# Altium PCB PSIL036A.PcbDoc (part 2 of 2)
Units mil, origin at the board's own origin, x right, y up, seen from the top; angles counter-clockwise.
Board outline 2820.01 x 3610.03 mil, 2 copper layers (Top Layer, Bottom Layer), stack 62 mil thick; 102 components, 95 nets, 316 pads, 73 vias.
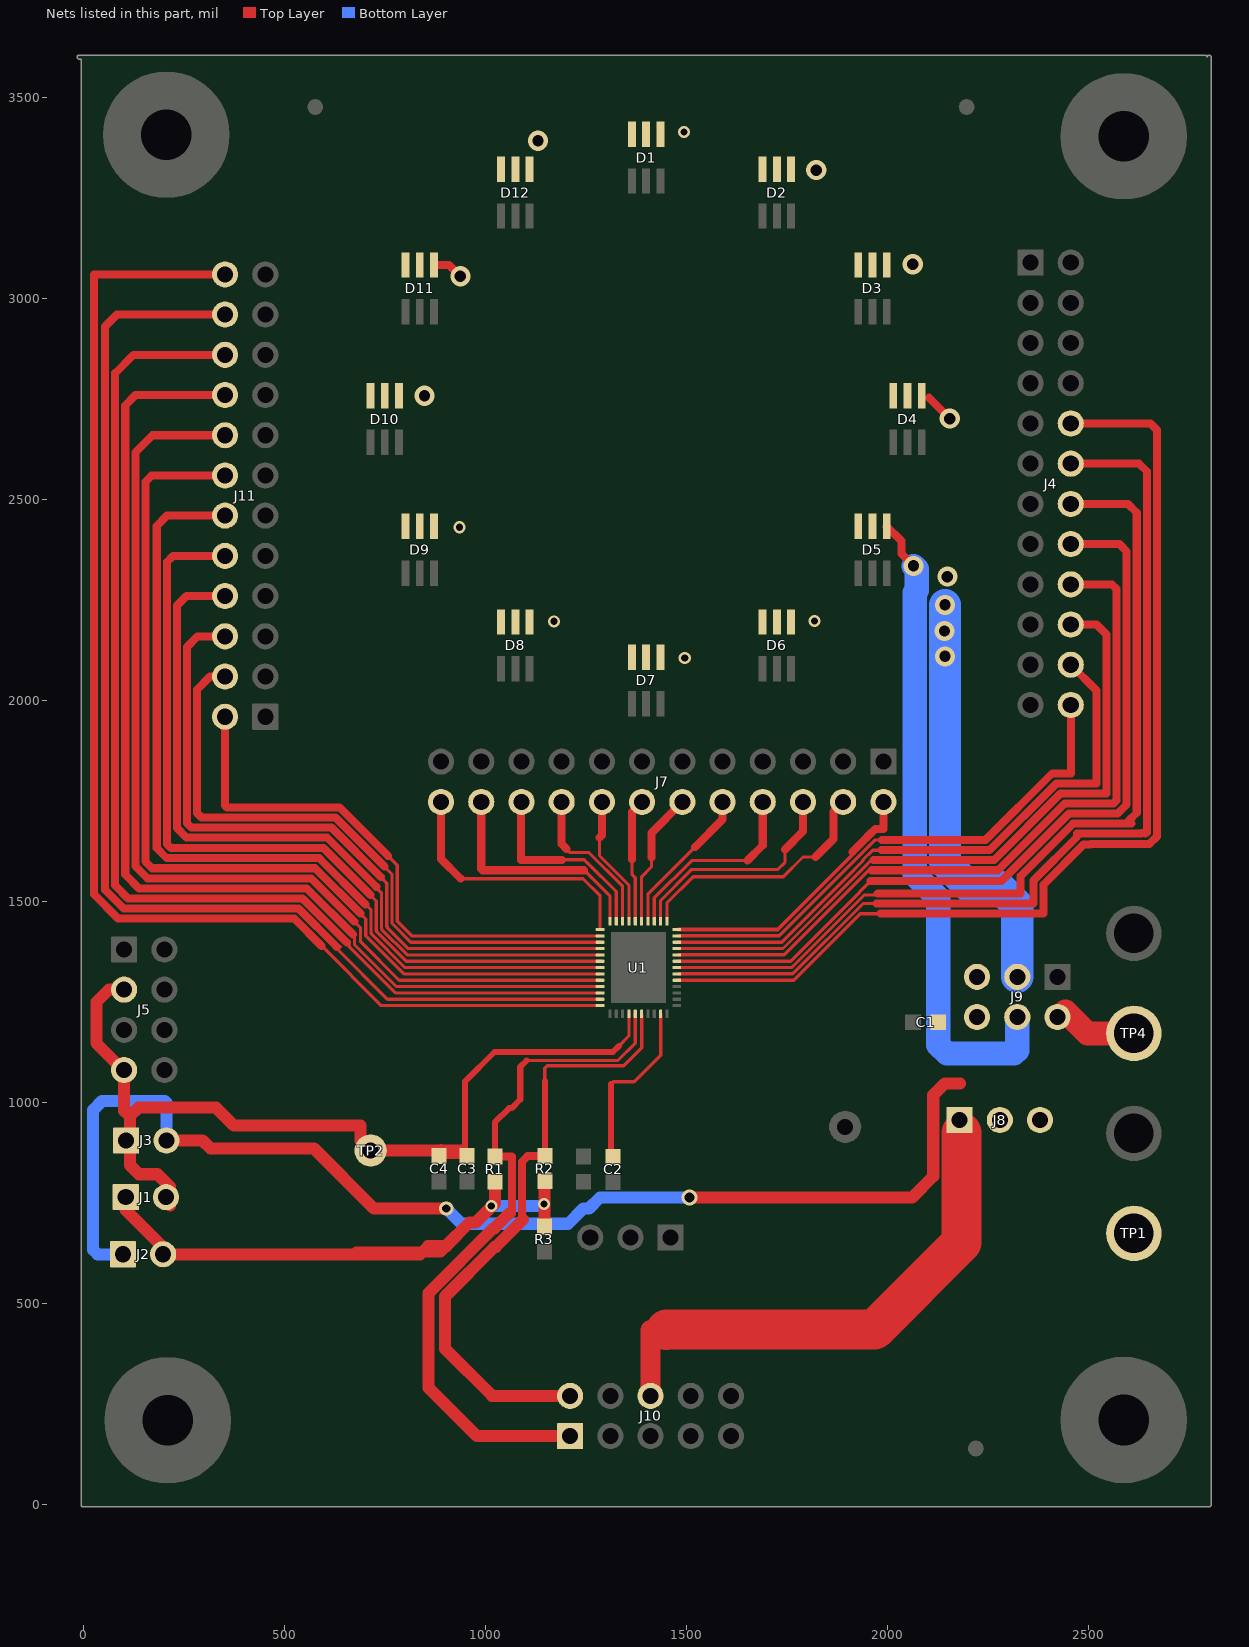
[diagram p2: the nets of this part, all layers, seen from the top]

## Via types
v1: diameter 50, hole 28, Top Layer to Bottom Layer, 48 vias
v2: diameter 19.68, hole 7.87, Top Layer to Bottom Layer, 16 vias
v3: diameter 30, hole 18, Top Layer to Bottom Layer, 7 vias
v4: diameter 35, hole 20, Top Layer to Bottom Layer, 1 vias
v5: diameter 40, hole 25, Top Layer to Bottom Layer, 1 vias

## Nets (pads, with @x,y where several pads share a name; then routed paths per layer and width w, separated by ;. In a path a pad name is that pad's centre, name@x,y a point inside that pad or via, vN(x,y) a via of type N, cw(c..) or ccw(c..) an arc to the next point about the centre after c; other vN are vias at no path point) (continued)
OUT4: J4.10 U1.5 | length 2612.8
  Top Layer w8: U1.5@1479.17,1304.63 1767.25,1304.63 1932.62,1470 1983,1470
  Top Layer w20: 1983,1470 2388,1470 2388,1542.07 2487.93,1642 2504.18,1642 2506,1643.82 2652,1643.82 2670,1661.82 2670,2673 2654,2689 J4.10@2455.99,2689
OUT5: J4.12 U1.6 | length 2434.9
  Top Layer w8: U1.6@1479.17,1320.38 1764.61,1320.38 1939.23,1495 1972.64,1495
  Top Layer w20: 1972.64,1495 2363,1495 2363,1552.42 2472,1661.42 2472,1668.82 2630.64,1668.82 2631.82,1670 ; J4.12@2455.99,2589 2626,2589 2645,2570 2645,1672.18 2641.64,1668.82
OUT6: J4.14 U1.7 | length 2258.7
  Top Layer w8: U1.7@1479.17,1336.13 1761.97,1336.13 1942.38,1516.53 1972.53,1516.53 1976,1520
  Top Layer w20: 1976,1520 2331,1520 2331,1563.18 2461.64,1693.82 2606.82,1693.82 2599.83,1700.82 2620,1720.99 2620,2467 2598,2489 J4.14@2455.99,2489
OUT7: J4.16 U1.8 | length 2053.7
  Top Layer w8: U1.8@1479.17,1351.87 1759.34,1351.87 1931.23,1523.77 1931.23,1524.3 1958.47,1551.53
  Top Layer w20: 1958.47,1551.53 2284,1551.53 2451.29,1718.82 2572.65,1718.82 2595,1741.17 2595,2371 2577,2389 J4.16@2455.99,2389
OUT8: J4.18 U1.9 | length 1894
  Top Layer w8: U1.9@1479.17,1367.62 1743.01,1367.62 1953.38,1578 1961,1578
  Top Layer w20: 1961,1578 2275.11,1578 2440.93,1743.82 2561.82,1743.82 2570,1752 2570,2277 2558,2289 J4.18@2455.99,2289
OUT9: J4.20 U1.10 | length 1720.6
  Top Layer w8: U1.10@1479.17,1383.37 1740.37,1383.37 1942,1585 1942,1585.87 1959.13,1603 1965,1603
  Top Layer w20: 1965,1603 2264.76,1603 2430.76,1769 2519,1769 ; J4.20@2455.99,2189 2520,2189 2545,2164 2545,1768.82 2519,1768.82
OUT10: J4.22 U1.11 | length 1527.9
  Top Layer w8: U1.11@1479.17,1399.12 1737.73,1399.12 1897.47,1558.85 1897.47,1559.72 1939.37,1601.63 1939.37,1604.24 1963.13,1628 1985,1628
  Top Layer w20: 1985,1628 2254.4,1628 2420.4,1794 2520,1794 2520,2024.99 J4.22@2455.99,2089
OUT11: J4.24 U1.12 | length 1314.7
  Top Layer w8: U1.12@1479.17,1414.87 1730.87,1414.87 1968.13,1652.13 1968.13,1653 1986,1653
  Top Layer w20: 1986,1653 2244.05,1653 2410.05,1819.01 2455.99,1819.01 J4.24@2455.99,1989
OUT12: J7.2 U1.13 | length 690
  Top Layer w9: U1.13@1479.17,1430.61 1727.52,1430.61 1916.95,1620.05
  Top Layer w15: J7.2@1990,1748 J7.2@1994,1744
  Top Layer w20: 1913.07,1623.94 1949.13,1660 1949.13,1660.87 1960.26,1672 1961.13,1672 1970.13,1681 1990,1681 J7.2@1990,1748
OUT13: J7.4 U1.14 | length 620.8
  Top Layer w8: U1.14@1451.61,1458.17 1451.61,1496.61 1517,1562 1741,1562 1790,1611 1821,1611
  Top Layer w20: 1821,1611 1866,1656 1866,1724 J7.4@1890,1748
OUT14: J7.6 U1.15 | length 562.5
  Top Layer w8: U1.15@1435.87,1458.17 1435.87,1502.87 1513,1580 1728,1580 1745,1597 1745,1630
  Top Layer w20: 1745,1630 1790,1675 J7.6@1790,1748
OUT15: J7.8 U1.16 | length 495.8
  Top Layer w8: U1.16@1420.12,1458.17 1420.12,1509.12 1513,1602 1652,1602
  Top Layer w15: J7.8@1681,1739 J7.8@1690,1748
  Top Layer w20: 1652,1602 1690,1640 J7.8@1690,1748
OUT16: J7.10 U1.17 | length 382.3
  Top Layer w8: U1.17@1404.37,1458.17 1404.37,1518.37 1522,1636
  Top Layer w15: J7.10@1590,1748 J7.10@1601,1737
  Top Layer w20: 1522,1636 1590,1704 J7.10@1590,1748
OUT17: J7.12 U1.18 | length 331.8
  Top Layer w8: U1.18@1388.62,1458.17 1388.62,1561.62 1413,1586 1413,1610
  Top Layer w20: 1413,1610 1413,1671 J7.12@1490,1748
OUT18: J7.14 U1.19 | length 303.4
  Top Layer w8: 1365,1605 1365,1567 1372.87,1559.13 U1.19@1372.87,1458.17
  Top Layer w20: 1365,1605 1365,1723 J7.14@1390,1748
OUT19: J7.16 U1.20 | length 322.6
  Top Layer w8: 1284,1659 1284,1614.38 1357.13,1541.26 U1.20@1357.13,1458.17
  Top Layer w20: 1284,1659 1290,1665 J7.16@1290,1748
OUT20: J7.18 U1.21 | length 380.1
  Top Layer w8: 1202,1631 1211,1622 1258,1622 1341.38,1538.62 U1.21@1341.38,1458.17
  Top Layer w20: J7.18@1190,1748 1190,1643 1202,1631
OUT21: J7.20 U1.22 | length 480.7
  Top Layer w8: 1191,1604 1246,1604 1253,1597 1253.87,1597 1325.63,1525.24 U1.22@1325.63,1458.17
  Top Layer w20: J7.20@1090,1748 1089,1747 1089,1604 1191,1604
OUT22: J7.22 U1.23 | length 570.5
  Top Layer w8: 1246,1578 1309.88,1514.12 U1.23@1309.88,1458.17
  Top Layer w20: J7.22@990,1748 990,1581 993,1578 1246,1578
OUT23: J7.24 U1.24 | length 659.4
  Top Layer w8: 939,1557 1243,1557 1285.53,1514.47 U1.24@1285.53,1430.49
  Top Layer w20: J7.24@890,1748 890,1606 939,1557
OUT24: J11.2 U1.25 | length 1369.3
  Top Layer w8: 757.95,1613.95 781.03,1590.88 781.03,1451.38 817.68,1414.74 U1.25@1285.53,1414.74
  Top Layer w20: J11.2@353,1959.76 353,1739 358,1734 637.91,1734 757.95,1613.95
OUT25: J11.4 U1.26 | length 1597.8
  Top Layer w8: 749.28,1587.28 768.03,1568.52 768.03,1446 815.04,1398.99 U1.26@1285.53,1398.99
  Top Layer w20: J11.4@353,2059.76 315.76,2059.76 283,2027 283,1720 294,1709 627.55,1709 749.28,1587.28
OUT26: J11.6 U1.27 | length 1765
  Top Layer w8: 740.1,1561.1 755.03,1546.16 755.03,1439.51 755.03,1438.51 756.03,1437.51 756.03,1435.51 808.29,1383.24 U1.27@1285.53,1383.24
  Top Layer w20: J11.6@353,2159.76 284.76,2159.76 258,2133 258,1695 269,1684 617.2,1684 740.1,1561.1
OUT27: J11.8 U1.28 | length 1919.5
  Top Layer w8: 727.5,1535.5 742.03,1520.97 742.03,1433.12 743.03,1432.12 743.03,1430.12 805.66,1367.5 U1.28@1285.53,1367.5
  Top Layer w20: J11.8@353,2259.76 256.76,2259.76 233,2236 233,1683 257,1659 606.84,1659 728.92,1536.92
OUT28: J11.10 U1.29 | length 2094.8
  Top Layer w8: 714.24,1516.24 729.03,1501.45 729.03,1427.74 730.03,1426.74 730.03,1424.74 803.02,1351.75 U1.29@1285.53,1351.75
  Top Layer w20: J11.10@353,2359.76 223.76,2359.76 208,2344 208,1643.36 218.36,1633 597.49,1633 714.24,1516.24
OUT29: J11.12 U1.30 | length 2241.2
  Top Layer w8: 702.07,1493.07 716.03,1479.1 716.03,1422.35 717.03,1421.35 ; 716.03,1420.35 800.38,1336 U1.30@1285.53,1336
  Top Layer w20: J11.12@353,2459.76 208.44,2459.76 183,2434.32 183,1633 208,1608 587.13,1608 702.07,1493.07
OUT30: J11.14 U1.31 | length 2420.4
  Top Layer w8: 689.39,1470.39 703.03,1456.74 703.03,1414.97 797.75,1320.25 U1.31@1285.53,1320.25
  Top Layer w20: J11.14@353,2559.76 170.44,2559.76 154.68,2544 154.68,1599.32 171,1583 576.78,1583 689.39,1470.39
OUT31: J11.16 U1.32 | length 2563.3
  Top Layer w8: 674.21,1450.21 690.03,1434.39 690.03,1399.97 785.5,1304.5 U1.32@1285.53,1304.5
  Top Layer w20: J11.16@353,2659.76 172.44,2659.76 129.68,2617 129.68,1588.32 160,1558 566.42,1558 674.21,1450.21
OUT32: J11.18 U1.33 | length 2734.2
  Top Layer w8: 671.03,1418.03 671.03,1413.19 674.68,1409.55 674.68,1393.32 779.24,1288.76 U1.33@1285.53,1288.76
  Top Layer w20: J11.18@353,2759.76 130.44,2759.76 104.68,2734 104.68,1567.32 139,1533 556.07,1533 671.03,1418.03
OUT33: J11.20 U1.34 | length 2885.3
  Top Layer w8: 655.68,1398.03 661.68,1392.03 661.68,1387.94 776.61,1273.01 U1.34@1285.53,1273.01
  Top Layer w20: J11.20@353,2859.76 125.44,2859.76 79.68,2814 79.68,1539.68 111.36,1508 545.71,1508 655.68,1398.03
OUT34: J11.22 U1.35 | length 3061.5
  Top Layer w8: 630.68,1383.32 756.74,1257.26 U1.35@1285.53,1257.26 ; 630.68,1387.68 639.16,1387.68
  Top Layer w20: J11.22@353,2959.76 84.52,2959.76 54.68,2929.92 54.68,1529.32 101,1483 535.36,1483 630.68,1387.68
OUT35: J11.24 U1.36 | length 3241.2
  Top Layer w8: 593,1390 741.49,1241.51 U1.36@1285.53,1241.51
  Top Layer w20: J11.24@353,3059.76 26.76,3059.76 26.76,1518.24 87,1458 525,1458 593,1390
SCL: J10.2 R2.1 U1.42 | length 1537
  Top Layer w8: 1148,1054 1148,1086 1154,1092 1344,1092 1388.87,1136.87 U1.42@1388.87,1220.84
  Top Layer w15: R2.1@1148,867.5 1148,1054
  Top Layer w20: 1091,706.57 1091,852.99 1105.5,867.5 R2.1@1148,867.5
  Top Layer w30: 1094.21,709.79 1091,706.57 1026.18,641.75 1023.75,641.75 900,518 900,388 1017,271 J10.2@1211,271
SDA: J10.1 R1.1 U1.41 | length 1744.6
  Top Layer w8: 1103,1105 1330,1105 1373.13,1148.13 U1.41@1373.13,1220.84
  Top Layer w15: R1.1@1024,866.5 1024,951 1059.5,986.5 1065.5,986.5 1087,1008 1087,1089 1103,1105
  Top Layer w20: R1.1@1024,866.5 1065.85,866.5 1067,865.35 1066,864.35 1066,724 1064.54,722.54
  Top Layer w30: 1061,726.07 1022.46,687.54 1020.04,687.54 859,526.5 859,291 979,171 J10.1@1211,171
VBG: D1.5 D1.6 D2.5 D2.6 D3.5 D3.6 D4.5 D4.6 D5.5 D5.6 D6.5 D6.6 D7.5 D7.6 D8.5 D8.6 D9.5 D9.6 D10.5 D10.6 D11.5 D11.6 D12.5 D12.6 J9.3 | length 1042.2
  Bottom Layer w80: v1(2143,2238) v1(2143,2110) 2143,1597.82 2202.34,1538.48 2275.09,1538.48 2323,1490.57 J9.3@2323,1313
  other v1: 2142,2173 2149,2308
VCAP: C2.1 U1.45 | length 438.9
  Top Layer w8: 1313,1047 1318,1052 1370,1052 1436.12,1118.12 U1.45@1436.12,1220.84
  Top Layer w15: 1313,1047 1313,870.5 C2.1@1318,865.5
VCC: C3.1 C4.1 J1.2 J3.1 J5.3 J5.7 TP2.1 U1.40 | length 2358.4
  Top Layer w8: 1332.17,1140.83 1357.38,1166.04 U1.40@1357.38,1220.84
  Top Layer w15: C4.1@896,875.2 904,867.2 C3.1@955,867.2 C3.1@962,867.2 ; C3.1@950,874.5 950,1053 1023,1126 1317.33,1126 1332.17,1140.83
  Top Layer w30: J5.3@100,1281 64,1281 33,1250 33,1148 100,1081 J5.7@102,1081 102,980 116,966 ; J1.2@216,744 216,791 185,822 139,822 116,845 116,966 ; C4.1@889.5,881.7 C4.1@896,875.2 ; C3.1@943.5,881 TP2.1@715,881 690,906 690,943 375,943 330,988 138,988 116,966
VIN_EXT: J8.3 TP1.1
VINL: J8.1 J10.6 | length 1299.9
  Top Layer w50: J10.6@1411,271 1411,435 1450,435
  Top Layer w100: 1450,435 1451,436 1968,436 2184,652 J8.1@2184,925
VLED: C1.1 J2.1 J3.2 J8.2 J9.5 J9.6 | length 3036
  Top Layer w30: J3.2@207,906 297,906 317,886 574,886 723,737 v4(903,737) ; v5(1508,764) 2061,764 2114,817 2114,1019 2143,1048 2181,1048
  Bottom Layer w30: J2.1@99,623 36,623 25,634 25,982 47,1004 203,1004 207,1000 J3.2@207,906 ; v4(903,737) 941,699 1206,699 1244,737 1258,737 1285,764 v5(1508,764)
VMCU: J1.1 J2.2 R1.2 R2.2 R3.2 | length 1570.2
  Top Layer w30: J1.1@106,765 106,733 199,640 J2.2@199,623 675.44,623 ; R1.2@1024,803.5 1024,750 975.75,701.75 960.5,701.75 902.38,643.62 ; R3.2@1147,705.5 1147,803.5 R2.2@1148,804.5 ; 675.44,623 838.01,623 842.01,627 ; 675.44,623 679.44,627 842.01,627 ; 842.01,627 844.5,629.5 ; 844.5,629.5 888.25,629.5 901.75,643 ; 844.5,629.5 858.01,643 901.75,643 ; 901.75,643 903,643 902.38,643.62 ; 901.75,643 902.38,643.62
  Bottom Layer w30: v3(1015,743) v3@1141,743
  other v3: 1146,748
VR: D1.4 D2.4 D3.4 D4.4 D5.4 D6.4 D7.4 D8.4 D9.4 D10.4 D11.4 D12.4 J9.4 | length 1789.1
  Top Layer w20: D11.4@872.53,3083.07 909.93,3083.07 v1(938,3055) ; D5.4@1998.33,2433.07 2035,2396.4 2035,2365 v1(2065,2335) ; 2103,2753 v1(2155,2701)
  Bottom Layer w60: v1(2065,2335) 2072.97,2327.03 2072.97,2274.03 2068,2269.07 2068,1566.75 2126.5,1508.25 2126.5,1143.5 2148,1122 2315,1122 2323,1130 J9.4@2323,1213
  other v1: 849,2758 2063,3085 1823,3319 1131,3392
  other v3: 1496,2106 1171,2197 1819,2198 936,2431 1494,3414
VR_EXT: J9.2 TP4.1 | length 188.6
  Top Layer w60: J9.2@2443,1227 2497.67,1172.33 TP4.1@2609,1172.33
pads on no net: FID1.1 FID2.1 FID3.1 H1.0 H2.1 H3.0 H4.1 H5.0 H6.1 H7.0 H8.1 J9.1 SH1.0 SH2.0 SH3.0 SH4.0 SH5.0 SH6.0 SH7.0 SH8.0 SH9.0 SH10.0 SH11.0 SH12.0 SH13.0 SH14.0 SH15.0 SH16.0 SH17.0 SH18.0 SH19.0 SH20.0 SH21.0 SH22.0 SH23.0 SH24.0 SH25.0 SH26.0 SH27.0 SH28.0 SH29.0 SH30.0 SH31.0 SH32.0 SH33.0 SH34.0 SH35.0 SH36.0 SH37.0 SH38.0 SH39.0 SH40.0 SH41.0 SH42.0 SH43.0 SH44.0 U1.

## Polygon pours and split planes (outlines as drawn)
VBG on Top Layer "VBG_L01_P024" (solid, remove dead copper, pour order 24): 1052,2147 1266,2147 1268,2145 1259,2136 1259,2023 1637,2023 1654,2040 1654,2127 1858,2127 1896,2165 1896,2365 2084,2365 2098,2351 2140,2393 2140,3118 1765,3493 984,3493 897,3406 897,3238 866,3207 659,3207 659,2169 679,2149
VBG on Top Layer "VBG_L01_P026" (solid, remove dead copper, pour order 26): 1966,2558 1966,2085 2015,2036 2035,2056 2271,2056 2271,2527 2252,2546 1976,2546
GND on Top Layer "GND_L01_P032" (solid, remove dead copper, pour order 32): 13,3604 17,3600 2800,3600 2800,11 2789,0 0,0 0,3559.6 12.24,3571.83
VR on Bottom Layer "VR_L02_P028" (solid, remove dead copper, pour order 28): 801,3164 801,2300 1044,2057 1751.49,2057 1926.49,2232 2055,2232 2099,2276 2099,2628.36 2097.36,2630 2125.36,2658 2205,2658 2205,3033 2062,3176 2062,3195 1902,3195 1896,3189 1869,3216 1869,3399 1583,3399 1529,3453 1529,3459 1067,3459 804,3196 804,3164
GND on Bottom Layer "GND_L02_P030" (solid, remove dead copper, pour order 30): -15,3600 -3,3612 2801,3612 2801,1 2800,0 2787,13 2,13 2,3598 0,3600

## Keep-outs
Keep-Out Layer:
  lines w10: -10,3600 2790,3600 ; 0,3600 0,0 2800,0 2800,3600
  text ".Layer_Name" at -673,-1908.49 h60

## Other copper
Top Layer:
  rectangle net VINL: 1379,262 1443,476.65
  rectangle net VIN_EXT: 2393,598 2690,725
  rectangle net VIN_EXT: 2390.86,621 2508,907
  rectangle net VCC: 881,854.4 962,890.7
  rectangle net VLED: 2169,1127 2279,1352
  rectangle net VLED: 2171,1028 2280,1208
  rectangle net VLED: 2165,1010 2365,1119
  rectangle net VIN_EXT: 2397,809 2502,1000
  rectangle net VLED: 2115,1159 2187,1239
  rectangle net VBG: 700,2734.95 756,2823
  rectangle net VR: 781,2725 874,2790
  rectangle net VBG: 795,2410 842,2519
  rectangle net VR: 873,2403 955,2471
  rectangle net VR: 1108,2167 1190,2236
  rectangle net VR: 1435,2072 1530,2149
  rectangle net VR: 1761,2165 1848,2237
  rectangle net VR: 2081,2733 2122,2785
  rectangle net VR: 1993,3048 2098,3133
  rectangle net VR: 1753,3290 1860,3355
  rectangle net VR: 1437,3377 1519,3440
  rectangle net VR: 1107,3295 1149,3411
  rectangle net VBG: 2099,2042 2199,2377
  rectangle net VLED: 2242,892 2330,1128
  rectangle net VINL: 2139,865 2228,964
  rectangle net VR_EXT: 2399,1126 2633,1229
  rectangle net VIN_EXT: 2348,898 2464,993
  text ".Layer_Name" at -673,-1908.49 h60
Bottom Layer:
  rectangle net VBG: 2114,2104 2186,2358
  text ".Layer_Name" at -673,-1908.49 h60

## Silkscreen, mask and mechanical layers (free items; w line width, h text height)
Top Overlay:
  text "EXT" at 2437,1392 h40 r90
  text "VLED" at 2335,1383 h40 r90
  text "3.3V" at 2230,1380 h40 r90
  text "EN" at 2036,1102 h40
  text "LP5036EVM" at 1647,561 h108.27
  text "PSIL036A" at 1643,476 h80
  text "2.5V-5.5V" at 2473,442 h72.83
  text "SCL" at 1030,256 h40
  text "SDA" at 1015,149 h40
  text ".Layer_Name" at -673,-1908.49 h60
Top Paste:
  text ".Layer_Name" at -673,-1908.49 h60
Bottom Paste:
  text ".Layer_Name" at -673,-1908.49 h60
Top Solder:
  text ".Layer_Name" at -673,-1908.49 h60
  text ".Layer_Name" at -673,-1908.49 h60
Bottom Solder:
  text ".Layer_Name" at -673,-1908.49 h60
Drill Guide:
  text ".Layer_Name" at -673,-1908.49 h60
M1 Board Outline:
  lines w10: -3,3598 2797,3598 ; 0,3600 0,0 2800,0 2800,3600
  text ".Layer_Name" at -673,-1908.49 h60
M2 Board Dimensions:
  rectangle: -1125,-1450 -750,-1325
  rectangle: -1250,-1325 -1125,-1200
  lines w7: -1250,-1325 -250,-1325 ; -1125,-1450 -1125,-1200 ; -1000,-1450 -1000,-1200 ; -750,-1450 -750,-1200 ; -500,-1450 -500,-1200 ; -1250,-1450 -1250,-1200 -250,-1200 -250,-1450 -1250,-1450
  text ".Layer_Name" at -673,-1908.49 h60
M3 3D STEP Top:
  text ".Layer_Name" at -673,-1908.49 h60
M4 3D STEP Bottom:
  text ".Layer_Name" at -673,-1908.49 h60
M5 Assembly Top:
  lines w10: -1542,-1980.17 5058,-1980.17 ; -1542,-1776.83 5060,-1776.83 ; -1542,-1573.5 -1542,-2183.5 2463,-2183.5 5060,-2183.5 5060,-1573.5 -1541.5,-1573.5 -1541.5,-2183.5 34,-2183.5 ; 923,-2183.5 923,-1573.5 ; 2190,-1776.83 2190,-1573.5 ; 3030,-1776.83 3030,-1573.5 ; 3652,-2190 3652,-1987.17
  text "COMPONENTS MARKED 'DNP' SHOULD NOT BE POPULATED." at -96.5,-1368.5 h60
  text "ASSEMBLY VARIANT:" at -97,-1484 h60
  text ".VariantName" at 939,-1484 h60
  text "PCB VIEWED FROM TOP SIDE" at -1478.5,-1705.67 h60
  text "BOARD #:" at 998,-1705.67 h60
  text ".PRJ_Number" at 1543.5,-1705.67 h60
  text "REV:" at 2388,-1705.67 h60
  text ".PCB_Rev" at 2679.5,-1705.67 h60
  text "SVN REV:" at 3226,-1705.67 h60
  text ".VersionControl_RevNumber" at 3732,-1705.67 h60
  text "TID #:" at 998,-1909 h60
  text ".TID" at 1543.5,-1909 h60
  text "PLOT NAME =" at -1478.5,-2114.34 h60
  text ".plot_File_Name" at -673,-2114.34 h60
  text "GENERATED    :" at 1000,-2114.34 h60
  text ".Print_Date" at 1869.5,-2114.34 h60
  text ".Print_Time" at 2598.5,-2114.34 h60
  text "TEXAS INSTRUMENTS" at 3863,-2114.34 h60
M6 Assembly Bottom:
  lines w10: -1542.5,-1777.33 5059.5,-1777.33 ; -1540.5,-1980.67 5059.5,-1980.67 ; -134.5,-2190.5 -134.5,-1987.67 ; 487.5,-1777.33 487.5,-1574 ; 1327.5,-1777.33 1327.5,-1574 ; 2594.5,-2184 2594.5,-1574 ; 3483.5,-2184 5059,-2184 5059,-1574 -1542.5,-1574 -1542.5,-2184 1054.5,-2184 5059.5,-2184 5059.5,-1574
  text "COMPONENTS MARKED 'DNP' SHOULD NOT BE POPULATED." at 4852,-1368 h60
  text ".VariantName" at 3808,-1484 h60
  text "ASSEMBLY VARIANT:" at 4847,-1484 h60
  text ".VersionControl_RevNumber" at -214.5,-1706.17 h60
  text "SVN REV:" at 291.5,-1706.17 h60
  text ".PCB_Rev" at 838,-1706.17 h60
  text "REV:" at 1129.5,-1706.17 h60
  text ".PRJ_Number" at 1974,-1706.17 h60
  text "BOARD #:" at 2519.5,-1706.17 h60
  text "PCB VIEWED FROM BOTTOM SIDE" at 4996,-1706.17 h60
  text ".TID" at 1974,-1909.5 h60
  text "TID #:" at 2519.5,-1909.5 h60
  text "TEXAS INSTRUMENTS" at -345.5,-2114.84 h60
  text ".Print_Time" at 919,-2114.84 h60
  text ".Print_Date" at 1648,-2114.84 h60
  text "GENERATED    :" at 2517.5,-2114.84 h60
  text ".plot_File_Name" at 4190.5,-2114.84 h60
  text "PLOT NAME =" at 4996,-2114.84 h60
M9 Title Sheet:
  drawing of 57 lines, arcs and shapes, not listed
  text "1" at -510.16,6986.5 h70
  text "2" at 1985.5,6986.5 h70
  text "3" at 4474.84,6986.5 h70
  text "4" at 6981.51,6986.5 h70
  text "5" at 9480.5,6986.5 h70
  text "6" at 11985.5,6986.5 h70
  text "A" at -1666.5,5843.5 h70
  text "A" at 13133.5,5843.5 h70
  text "B" at -1666.5,3463.5 h70
  text "B" at 13133.5,3463.5 h70
  text "C" at -1666.5,1088.5 h70
  text "C" at 13133.5,1088.5 h70
  text "PROJECT TITLE:" at 10093.5,-772.5 h45
  text ".PRJ_Title" at 10143.5,-905.83 h70
  text "DESIGNED FOR:" at 10093.5,-1073.5 h45
  text ".PRJ_Customer" at 10143.5,-1213.5 h70
  text "D" at -1666.5,-1281.5 h70
  text "D" at 13133.5,-1281.5 h70
  text "FILE NAME:" at 10093.5,-1373.5 h45
  text ".PCB_File_Name_No_Path" at 10143.5,-1493.5 h70
  text "Texas Instruments (TI) and/or its licensors do not warrant the accuracy or completeness of this specification" at 5124,-1655.34 h45
  text "ENGINEER:" at 10093.5,-1663.5 h45
  text "LAYOUT BY:" at 11598.5,-1663.5 h45
  text "or any information contained therein. TI and/or its licensors do not warrant that this design will meet" at 5079.01,-1768 h45
  text ".PRJ_Engineer" at 10143.5,-1818.49 h70
  text ".PCB_Layout" at 11649,-1818.49 h70
  text "the specifications, will be suitable for your application or fit for any particular purpose, or will operate in" at 5079.01,-1880.67 h45
  text ".Layer_Name" at -673,-1908.49 h60
  text "ALTIUM DESIGNER VERSION:" at 11598.5,-1973.5 h45
  text "an implementation. TI and/or its licensors do not warrant that the design is production worthy. You should" at 5079.01,-1993.33 h45
  text "completely validate and test your design implementation to confirm the system functionality for your application." at 5124,-2106 h45
  text ".print_Scale" at 10143.5,-2106.83 h70
  text ".Application_BuildNumber" at 11649,-2106.83 h70
  text "1" at -510.16,-2313.5 h70
  text "2" at 1985.5,-2313.5 h70
  text "3" at 4474.84,-2313.5 h70
  text "4" at 6981.51,-2313.5 h70
  text "5" at 9480.5,-2313.5 h70
  text "6" at 11985.5,-2313.5 h70
M10 Fab Notes:
  drawing of 173 lines, arcs and shapes, not listed
  text "DESIGN INFORMATION" at 11128.02,5151 h60
  text "MIN. TRACK WIDTH:" at 10483.46,4971 h60
  text "8" at 11579.7,4971 h60
  text "MIL" at 11734.46,4971 h60
  text "MIN. CLEARANCE:" at 10483.46,4839 h60
  text "mm" at 11734.46,4839 h60
  text "0.127" at 11419,4834 h60
  text "MIN. VIA PAD SIZE:" at 10483.46,4707 h60
  text "MIL" at 11734.46,4707 h60
  text "19.685" at 11378,4702 h60
  text "0.05mm (2MIL)" at 11178.46,4565.29 h60
  text "MINIMUM ANNULAR RING" at 10154.23,4561 h60
  text "EXTERNAL" at 11886.46,4561 h60
  text "PER" at 10354.23,4443 h60
  text "IPC-D-275 CLASS 2 LEVEL C" at 10574.23,4443 h60
  text "MIL, HOLES" at 12062.46,4330.71 h60
  text "+/-" at 11670,4330 h60
  text "+/-" at 12524,4330 h60
  text "REGISTRATION TOLERANCES:" at 10154.23,4325 h60
  text "METAL" at 11354,4325 h60
  text "5" at 11930.2,4325 h60
  text "3" at 12763.2,4325 h60
  text "MIL" at 12879.46,4325 h60
  text "+/-" at 12524,4212 h60
  text "HOLE SIZE TOLERANCE (UNLESS OTHERWISE SPECIFIED):" at 10154.23,4207 h60
  text "3" at 12763.2,4207 h60
  text "MIL" at 12879.46,4207 h60
  text "MATERIAL:" at 10079.46,3997.54 h60
  text "FR-4 High Tg" at 11065.9,3857.21 h60
  text "FR-408" at 10500.46,3848.64 h60
  text "OTHER" at 11988.46,3848.64 h60
  text "X" at 10911,3845 h60
  text "62 MIL (1.6mm) +/-10%" at 10820.56,3685.92 h60
  text "THICKNESS:" at 10154.23,3681.64 h60
  text "X" at 10692.4,3681.64 h60
  text "OTHER" at 12105.46,3681.64 h60
  text "TOLERANCE:" at 10154.23,3523.64 h60
  text "X" at 10993.53,3523.64 h60
  text "ANSI IPC-6012 TYPE 3 CLASS 2" at 11180.48,3523.64 h60
  text "OTHER +/-" at 11180.46,3367.64 h60
  text "BOW & TWIST:" at 10154.23,3210.64 h60
  text "X" at 10993.53,3210.64 h60
  text "ANSI IPC-6012 TYPE 3 CLASS 2" at 11180.48,3210.64 h60
  text "OTHER +/-" at 11180.46,3052.13 h60
  text "DRILLING:" at 10079.46,2913.64 h60
  text "REFERENCE:" at 10154.23,2796.64 h60
  text "X" at 10802.46,2796.64 h60
  text "AS SHOWN" at 10989.46,2796.64 h60
  text "X" at 11703.46,2796.64 h60
  text "NC_DRILL FILES" at 11840.46,2796.64 h60
  text "PTH COPPER THICKNESS:" at 10154.23,2638.64 h60
  text "X" at 11284.46,2638.64 h60
  text "20-30 um" at 11421.46,2638.64 h60
  text "OTHER" at 12138.46,2638.64 h60
  text "BOARD FINISH:" at 10079.46,2479.64 h60
  text "SILKSCREEN:" at 10234.68,2361.64 h60
  text "X" at 11183.46,2361.64 h60
  text "TOP" at 11309.46,2361.64 h60
  text "BOTTOM" at 11820.46,2361.64 h60
  text "SILKSCREEN COLOR:" at 10234.68,2194.64 h60
  text "X" at 11182.42,2194.64 h60
  text "WHITE" at 11309.46,2194.64 h60
  text "OTHER" at 11820.46,2194.64 h60
  text "X" at 11310,2040 h60
  text "RED" at 11440.46,2035.44 h60
  text "OTHER" at 12058.46,2035.44 h60
  text "SOLDER RESIST COLOR:" at 10234.68,2024.64 h60
  text "X" at 11313.42,1865.44 h60
  text "MATTE" at 11440.46,1865.44 h60
  text "SEMI-GLOSS" at 12058,1864.8 h60
  text "IMMERSION GOLD (ENIG)" at 11140.46,1676.92 h60
  text "ENEPIG" at 12478,1673.64 h60
  text "SURFACE FINISH:" at 10079.46,1672.64 h60
  text "X" at 10953.51,1672.64 h60
  text "IMM. TIN/SILVER OR EQUIV" at 10409,1515.64 h60
  text "OTHER" at 11840.46,1515.64 h60
  text "ARRAY/PANEL:" at 10079.46,1336.64 h60
  text "CUT AND TRIM PER M1 BOARD OUTLINE" at 11140.46,1332.35 h60
  text "N.C. ROUTE" at 11140.46,1180.64 h60
  text "X" at 11819.46,1180.64 h60
  text "V. SCORE" at 12006.46,1180.64 h60
  text "CERTIFICATION:" at 10079.46,1043.64 h60
  text "MATERIALS AND WORKMANSHIP FOR ALL PCBS" at 10804.46,1043.64 h60
  text "TO MEET OR EXCEED THE REQUIREMENTS OF:" at 10804.46,945.64 h60
  text "X" at 10430.96,809.13 h60
  text "ANSI IPC-A-600F CLASS ->" at 10569.96,809.13 h60
  text "X" at 12209.02,809.13 h60
  text "2" at 12327.96,809.14 h60
  text "1" at 12012.96,807.64 h60
  text "3" at 12681.96,807.64 h60
  text "X" at 11245.02,649.64 h60
  text "RoHS" at 11381.96,649.64 h60
  text "OTHER" at 12026.36,649.64 h60
  text "PER ORDER" at 12423.42,649.64 h60
  text "ALL BOARDS MUST MEET OR EXCEED UL94-V0 REQUIREMENTS." at 10107,484 h60
  text "PCB MUST BEAR THE UL94V-0 UL REGISTERED MATERIAL ID NUMBER" at 10107,364 h60
  text "ADDITIONAL REQUIREMENTS:" at 10079.46,190.64 h60
  text "MICROSECTION:" at 10154.23,75.64 h60
  text "YES" at 11059.96,75.64 h60
  text "REQUIRED" at 11921.46,-80.51 h60
  text "BARE BOARD ELEC. TEST:" at 10154.23,-83.36 h60
  text "NONE" at 11459.96,-83.36 h60
  text "X" at 11794.46,-83.36 h60
  text "PER ORDER" at 12513.46,-83.36 h60
  text ".Layer_Name" at -673,-1908.49 h60
M11 Gerber Information:
  lines w10: -1542,-1980.17 5058,-1980.17 ; -1542,-1776.83 5060,-1776.83 ; -1542,-1573.5 -1542,-2183.5 2463,-2183.5 5060,-2183.5 5060,-1573.5 -1541.5,-1573.5 -1541.5,-2183.5 34,-2183.5 ; 923,-2183.5 923,-1573.5 ; 2190,-1776.83 2190,-1573.5 ; 3030,-1776.83 3030,-1573.5 ; 3652,-2190 3652,-1987.17
  text "ALL ARTWORK VIEWED FROM TOP SIDE" at -1478.5,-1705.67 h60
  text "BOARD #:" at 998,-1705.67 h60
  text ".PRJ_Number" at 1543.5,-1705.67 h60
  text "REV:" at 2388,-1705.67 h60
  text ".PCB_Rev" at 2679.5,-1705.67 h60
  text "SVN REV:" at 3226,-1705.67 h60
  text ".VersionControl_RevNumber" at 3732,-1705.67 h60
  text "LAYER NAME =" at -1478.5,-1908.49 h60
  text "TID #:" at 998,-1909 h60
  text ".TID" at 1543.5,-1909 h60
  text "PLOT NAME =" at -1478.5,-2114.34 h60
  text ".plot_File_Name" at -673,-2114.34 h60
  text "GENERATED    :" at 1000,-2114.34 h60
  text ".Print_Date" at 1869.5,-2114.34 h60
  text ".Print_Time" at 2598.5,-2114.34 h60
  text "TEXAS INSTRUMENTS" at 3863,-2114.34 h60
M12 Stackup:
  drawing of 191 lines, arcs and shapes, not listed
  text "Layer" at 4767.58,5219.8 h60
  text "Name" at 5177.49,5219.8 h60
  text "Material" at 6107.24,5219.8 h60
  text "Thickness" at 6967,5219.8 h60
  text "Constant" at 7616.84,5219.8 h60
  text "Board Layer Stack" at 8186.7,5219.8 h60
  text "1" at 4767.58,5099.8 h60
  text "Top Overlay" at 5177.49,5099.8 h60
  text "2" at 4767.58,4979.8 h60
  text "Top Solder" at 5177.49,4979.8 h60
  text "Solder Resist" at 6107.24,4979.8 h60
  text "0.40mil" at 6967,4979.8 h60
  text "3.5" at 7616.84,4979.8 h60
  text "3" at 4767.58,4859.8 h60
  text "Top Layer" at 5177.49,4859.8 h60
  text "Copper" at 6107.24,4859.8 h60
  text "1.40mil" at 6967,4859.8 h60
  text "4" at 4767.58,4739.8 h60
  text "Dielectric1" at 5177.49,4739.8 h60
  text "FR-4" at 6107.24,4739.8 h60
  text "59.20mil" at 6967,4739.8 h60
  text "4.8" at 7616.84,4739.8 h60
  text "5" at 4767.58,4619.8 h60
  text "Bottom Layer" at 5177.49,4619.8 h60
  text "Copper" at 6107.24,4619.8 h60
  text "1.40mil" at 6967,4619.8 h60
  text "6" at 4767.58,4499.8 h60
  text "Bottom Solder" at 5177.49,4499.8 h60
  text "Solder Resist" at 6107.24,4499.8 h60
  text "0.40mil" at 6967,4499.8 h60
  text "3.5" at 7616.84,4499.8 h60
  text "7" at 4767.58,4379.8 h60
  text "Bottom Overlay" at 5177.49,4379.8 h60
  text ".Layer_Name" at -673,-1908.49 h60
M13 Component Bodies Top:
  text ".Layer_Name" at -673,-1908.49 h60
M14 Component Bodies Bottom:
  text ".Layer_Name" at -673,-1908.49 h60
M15 Courtyards Top:
  text ".Layer_Name" at -673,-1908.49 h60
M16 Courtyards Bottom:
  text ".Layer_Name" at -673,-1908.49 h60
Drill Drawing:
  circle w10: c5613.63,1347.26 r16.56
  circle w10: c5613.63,1347.26 r27.59
  lines w10: 5586.04,1195.49 5641.23,1195.49 5641.23,1250.68 5586.04,1250.68 5586.04,1195.49 ; 5586.04,1443.84 5641.23,1443.84 5641.23,1499.03 5586.04,1499.03 5586.04,1443.84 ; 5586.04,1581.82 5599.83,1581.82 5613.63,1568.02 5627.43,1581.82 5641.23,1581.82 5627.43,1595.62 5641.23,1609.41 5627.43,1609.41 5613.63,1623.21 5599.83,1609.41 5586.04,1609.41 5599.83,1595.62 5586.04,1581.82 ; 5586.04,1705.99 5599.83,1705.99 5599.83,1692.2 5627.43,1692.2 5627.43,1705.99 5641.23,1705.99 5641.23,1733.59 5627.43,1733.59 5627.43,1747.39 5599.83,1747.39 5599.83,1733.59 5586.04,1733.59 5586.04,1705.99 ; 5586.04,1816.37 5586.04,1830.17 5599.83,1843.97 5586.04,1857.76 5586.04,1871.56 5599.83,1871.56 5613.63,1857.76 5627.43,1871.56 5641.23,1871.56 5641.23,1857.76 5627.43,1843.97 5641.23,1830.17 5641.23,1816.37 5627.43,1816.37 5613.63,1830.17 5599.83,1816.37 5586.04,1816.37 ; 5586.04,1968.14 5613.63,1940.55 5641.23,1968.14 5613.63,1995.74 5586.04,1968.14 ; 5586.04,2119.91 5641.23,2119.91 5613.63,2064.72 5586.04,2119.91 ; 5586.04,2188.9 5613.63,2202.7 5641.23,2188.9 5627.43,2216.5 5641.23,2244.09 5613.63,2230.29 5586.04,2244.09 5599.83,2216.5 5586.04,2188.9 ; 5597.07,1206.53 5630.19,1206.53 5630.19,1239.64 5597.07,1239.64 5597.07,1206.53
  lines w12: 5536,1158.24 8766.52,1158.24 ; 5536,2275.82 8766.52,2275.82 ; 5873.86,1034.06 5873.86,2400 ; 6205.86,1034.06 6205.86,2400 ; 6842.42,1034.06 6842.42,2400 ; 7101.53,1034.06 7101.53,2400 ; 7476.68,1034.06 7476.68,2400 ; 8200.06,1034.06 8200.06,2400 ; 5536,1034.06 8766.52,1034.06 8766.52,2400 5536,2400 5536,1034.06
  text "Symbol" at 5610.51,2313.08 h72
  text "Quantity" at 5911.11,2313.08 h72
  text "Finished Hole Size" at 6243.12,2313.08 h72
  text "Plated" at 6879.67,2313.08 h72
  text "Hole Type" at 7138.78,2313.08 h72
  text "Drill Layer Pair" at 7513.93,2313.08 h72
  text "Hole Tolerance" at 8237.32,2313.08 h72
  text "16" at 5911.11,2188.9 h60
  text "7.87mil (0.200mm)" at 6243.12,2188.9 h60
  text "PTH" at 6879.67,2188.9 h60
  text "Round" at 7138.78,2188.9 h60
  text "Top Layer - Bottom Layer" at 7513.93,2188.9 h60
  text "7" at 5911.11,2064.72 h60
  text "18.00mil (0.457mm)" at 6243.12,2064.72 h60
  text "PTH" at 6879.67,2064.72 h60
  text "Round" at 7138.78,2064.72 h60
  text "Top Layer - Bottom Layer" at 7513.93,2064.72 h60
  text "1" at 5911.11,1940.55 h60
  text "20.00mil (0.508mm)" at 6243.12,1940.55 h60
  text "PTH" at 6879.67,1940.55 h60
  text "Round" at 7138.78,1940.55 h60
  text "Top Layer - Bottom Layer" at 7513.93,1940.55 h60
  text "1" at 5911.11,1816.37 h60
  text "25.00mil (0.635mm)" at 6243.12,1816.37 h60
  text "PTH" at 6879.67,1816.37 h60
  text "Round" at 7138.78,1816.37 h60
  text "Top Layer - Bottom Layer" at 7513.93,1816.37 h60
  text "48" at 5911.11,1692.2 h60
  text "28.00mil (0.711mm)" at 6243.12,1692.2 h60
  text "PTH" at 6879.67,1692.2 h60
  text "Round" at 7138.78,1692.2 h60
  text "Top Layer - Bottom Layer" at 7513.93,1692.2 h60
  text "10" at 5911.11,1568.02 h60
  text "39.37mil (1.000mm)" at 6243.12,1568.02 h60
  text "PTH" at 6879.67,1568.02 h60
  text "Round" at 7138.78,1568.02 h60
  text "Top Layer - Bottom Layer" at 7513.93,1568.02 h60
  text "100" at 5911.11,1443.84 h60
  text "40.00mil (1.016mm)" at 6243.12,1443.84 h60
  text "PTH" at 6879.67,1443.84 h60
  text "Round" at 7138.78,1443.84 h60
  text "Top Layer - Bottom Layer" at 7513.93,1443.84 h60
  text "4" at 5911.11,1319.67 h60
  text "98.43mil (2.500mm)" at 6243.12,1319.67 h60
  text "PTH" at 6879.67,1319.67 h60
  text "Round" at 7138.78,1319.67 h60
  text "Top Layer - Bottom Layer" at 7513.93,1319.67 h60
  text "4" at 5911.11,1195.49 h60
  text "125.98mil (3.200mm)" at 6243.12,1195.49 h60
  text "PTH" at 6879.67,1195.49 h60
  text "Round" at 7138.78,1195.49 h60
  text "Top Layer - Bottom Layer" at 7513.93,1195.49 h60
  text "191 Total" at 5911.11,1071.32 h60
  text ".Layer_Name" at -673,-1908.49 h60
M17 Embedded Cavity:
  text ".Layer_Name" at -673,-1908.49 h60
M18 Embedded Assembly:
  text ".Layer_Name" at -673,-1908.49 h60
M19 Embedded Keepout:
  text ".Layer_Name" at -673,-1908.49 h60

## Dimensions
2800,0 to 0,0 on M2 Board Dimensions
0,3600 to 0,0 on M2 Board Dimensions
-1250,-1450 to -250,-1450 on M2 Board Dimensions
